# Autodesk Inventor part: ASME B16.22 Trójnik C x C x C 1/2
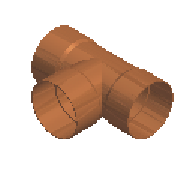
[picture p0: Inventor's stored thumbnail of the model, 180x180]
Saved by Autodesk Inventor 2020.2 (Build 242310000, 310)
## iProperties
Manager: www.cadconsulting.pl
Company: Fabian Stasiak CAD Consulting
NAME: PIPING: ASME B16.22 Tee C x C x C
DATA: <meta><inlinegroups number="1" deflen="34.0868"></inlinegroups><connections number="3"></connections><angles><a>3.14159265358979</a><a>1.5707963267949</a></angl
Created: 2014-02
Part Number: ASME B16.22 Trójnik C x C x C 1/2
Material: Miedź kuta
Description: Trójnik
Document SubType Name: Modeling
Standard: ASME B16.22
Designer: F.Stasiak
Standard Revision: 2001
Standards Organization: ANSI
Language: pl-PL
Size Designation: 1/2
Categories: <MemberInstance><Categories><Category DisplayName="Rury cienko- i grubościenne" InternalName="4347fa0f-2144-441d-94cd-e3e15c92b736" Mnemonic="TUBEANDPIPE"><Cate
Density: 1 g/cm^3
Appearance: Miedź - satynowa
Catalog Web Link: www.expertbooks.pl
IsCustomPart: 0
Author: F.Stasiak
Subject: Zbiór ćwiczeń. Autodesk Inventor 2020. Kurs Professional
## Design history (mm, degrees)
sketch "Sketch1"
  geometry: L1 (-68.174, 0)-(409.042, 0) reference; L2 (32.61, 7.341)-(15.142, 7.341); L3 (35.052, 8.75)-(32.61, 7.341); L4 (47.752, 8.75)-(35.052, 8.75); L5 (47.752, 8.014)-(47.752, 8.75); L6 (47.752, 8.014)-(35.052, 8.014); L7 (35.052, 8.014)-(35.052, 6.604); L8 (35.052, 6.604)-(12.7, 6.604); L9 (12.7, 6.604)-(12.7, 8.014); L10 (12.7, 8.014)-(0, 8.014); L11 (15.142, 7.341)-(12.7, 8.75); L12 (12.7, 8.75)-(0, 8.75); L13 (0, 8.75)-(0, 8.014); L14 (47.752, 8.014)-(47.752, 0); L15 (0, 0)-(0, 8.014)
  constraints: 28 end point, 4 collinear, 4 parallel, 2 perpendicular, 1 point on line
  dimensions: "d0" = 16.0274 diameter of L6 L1 (= F1); "d1" = 14.6812 diameter of L2 L1 (= O + 2 x T); "d2" = 17.5006 diameter of L4 L1 (= F1 + 2 x T); "d4" = 30 deg angle of L4 L3; "d5" = 12.7 distance of L4.start L3.start (= G); "d6" = 13.208 diameter of L8 L1 (= O); "d16" = 22.352 distance between parallel lines of L7 L9 (= 2 x H); "d17" = 12.7 distance between parallel lines of L14 L7 (= G); "d18" = 30 deg angle of L12 L11; "d19" = 12.7 distance between parallel lines of L15 L9 (= G)
revolve "Revolution1" stored, may be unused: angle "d123" = 90 deg
workplane "Work Plane1"
sketch "Sketch2"
  geometry: L1 (0, -34.087)-(0, 204.521) reference; L2 (-97.246, 0)-(16.208, 0) reference; L3 (0, 23.876)-(-8.75, 23.876); L4 (-8.75, 23.876)-(-8.75, 10.808); L5 (-7.341, 8.366)-(-7.341, 0); L6 (-8.75, 10.808)-(-7.341, 8.366); L7 (-8.014, 11.176)-(0, 11.176); L8 (-8.014, 23.876)-(-8.014, 11.176); L9 (-6.604, 11.176)-(-6.604, 0); 1 further point
  constraints: 14 end point, 6 point on line, 3 perpendicular, 2 parallel
  dimensions: "d8" = 23.876 distance from line of L3 point (0, 0) (= H + G); "d9" = 13.0683 distance of L3.end L4.end (= G + 0.5 x T); "d10" = 17.5006 diameter of L4 L1 (= F1 + 2 x T); "d11" = 30 deg angle of L4 L6; "d12" = 14.6812 diameter of L5 L1 (= O + 2 x T); "d13" = 12.7 distance between parallel lines of L3 L7 (= G); "d14" = 16.0274 diameter of L8 L1 (= F1); "d15" = 13.208 diameter of L9 L1 (= O)
revolve "Revolution2" stored, may be unused: angle "d174" = 90 deg
revolve "Revolution3" stored, may be unused: angle "d176" = 90 deg
revolve "Revolution4" stored, may be unused: angle "d184" = 90 deg
workaxis "Work Axis1"
workpoint "Work Point1"
workpoint "Work Point2"
workaxis "Work Axis2"
workpoint "Work Point3"
workpoint "Work Point4"
workaxis "Work Axis3"
workpoint "Work Point5"
workpoint "Work Point6"
body "Solid1"
other parameters: "O" = 13.208 [user parameter; used in 5 equation terms], "F1" = 16.0274 [user parameter; used in 4 equation terms], "G" = 12.7 [user parameter; used in 7 equation terms], "T" = 0.7366 [user parameter; used in 5 equation terms], "H" = 11.176 [user parameter; used in 3 equation terms], "d3" = 13.208 (= O), "d7" = 23.876 (= H + G), "Size_Designation" = 5 [user parameter]
